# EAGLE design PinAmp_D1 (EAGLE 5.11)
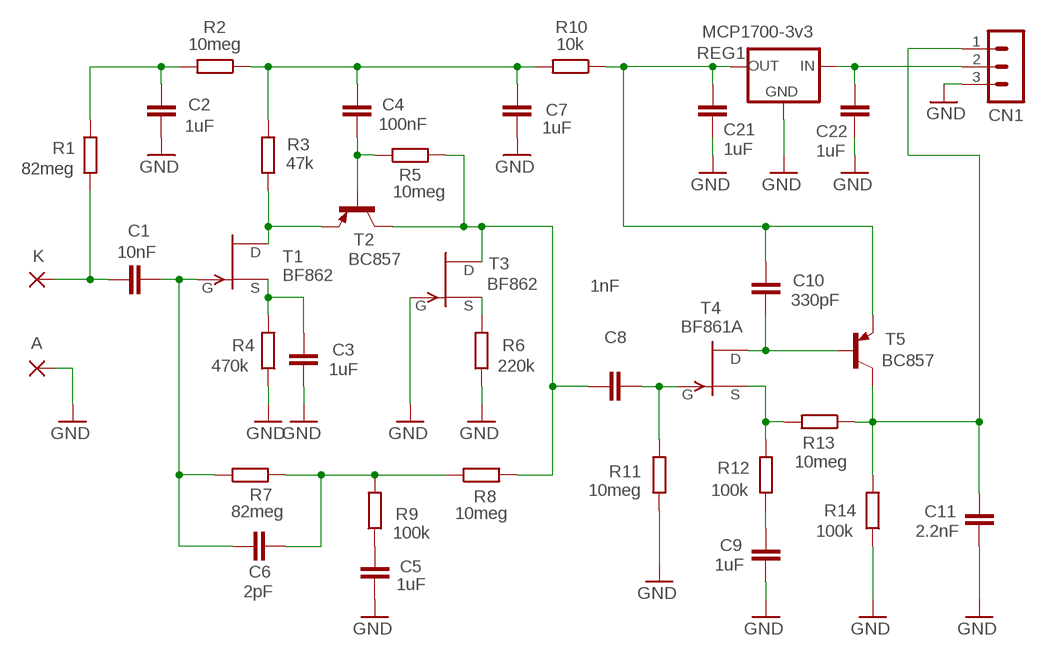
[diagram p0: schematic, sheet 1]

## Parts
A  A  WIREPAD1,6/0,8  [1,6/0,8]
C1  10nF  C-EUC0805  [C0805]
C2  1uF  C-EUC0603  [C0603]
C3  1uF  C-EUC0603  [C0603]
C4  100nF  C-EUC0603  [C0603]
C5  1uF  C-EUC0603  [C0603]
C6  2pF  C-EUC0603  [C0603]
C7  1uF  C-EUC0603  [C0603]
C8  1nF  C-EUC0603  [C0603]
C9  1uF  C-EUC0603  [C0603]
C10  330pF  C-EUC0603  [C0603]
C11  2.2nF  C-EUC0603  [C0603]
C21  1uF  C-EUC0603  [C0603]
C22  1uF  C-EUC0603  [C0603]
CN1  CN1  MA03-1W  [MA03-1W]
K  K  WIREPAD1,6/0,8  [1,6/0,8]
R1  82meg  R-EU_R0805  [R0805]
R2  10meg  R-EU_R0603  [R0603]
R3  47k  R-EU_R0603  [R0603]
R4  470k  R-EU_R0603  [R0603]
R5  10meg  R-EU_R0603  [R0603]
R6  220k  R-EU_R0603  [R0603]
R7  82meg  R-EU_R0805  [R0805]
R8  10meg  R-EU_R0805_L  [R0805_L]
R9  100k  R-EU_R0603  [R0603]
R10  10k  R-EU_R0603  [R0603]
R11  10meg  R-EU_R0603  [R0603]
R12  100k  R-EU_R0603  [R0603]
R13  10meg  R-EU_R0603  [R0603]
R14  100k  R-EU_R0603  [R0603]
REG1  MCP1700-3v3  MCP1700SOT23  [SOT23]
T1  BF862  BF861LR  [SOT23_L]
T2  BC857  -PNP-BC857  [SOT23_L]
T3  BF862  BF861LR  [SOT23_L]
T4  BF861A  BF861LR  [SOT23_L]
T5  BC857  -PNP-BC857  [SOT23_L]

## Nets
GND: A.1(P) C2.2 C3.1 C5.1 C7.2 C9.2 C11.2 C21.2 C22.2 CN1.3 R4.1 R6.1 R11.1 R14.1 REG1.1(GND) T3.3(G)
N$2: C2.1 R1.2 R2.2
N$3: C4.1 C7.1 R2.1 R3.2 R10.2
N$4: R3.1 T1.2(D) T2.2(E)
N$5: R6.2 T3.1(S)
N$6: C3.2 R4.2 T1.1(S)
N$7: C11.1 CN1.1 R13.1 R14.2 T5.3(C)
N$8: C6.2 R7.2 R8.1 R9.2
N$9: C4.2 R5.1 T2.1(B)
N$10: C5.2 R9.1
N$11: C1.2 C6.1 R7.1 T1.3(G)
N$12: C8.2 R11.2 T4.3(G)
N$13: C1.1 K.1(P) R1.1
N$15: C22.1 CN1.2 REG1.3(IN)
N$16: C8.1 R5.2 R8.2 T2.3(C) T3.2(D)
N$17: R12.2 R13.2 T4.1(S)
N$18: C9.1 R12.1
N$24: C10.1 T4.2(D) T5.1(B)
N$25: C10.2 C21.1 R10.1 REG1.2(OUT) T5.2(E)

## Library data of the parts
A = wirepad:WIREPAD: Wire PAD connect wire on PCB
C1-C11 C21 C22 = 00-LIVIO:C-EU: CAPACITOR, European symbol
CN1 = 03-con-lstb-M:MA03-1W
K = 00-LIVIO:WIREPAD: Wire PAD connect wire on PCB
R1-R14 = 00-LIVIO:R-EU_: RESISTOR, European symbol
REG1 = 00-LIVIO:MCP1700: Linear regulator Quescient courrent 1.8uA Input 2.3v to 6v Output 1.2v 1.8v 2.5v 3.0v 3.3v 5.0v
T1 T3 T4 = 00-LIVIO:BF861
T2 T5 = 00-LIVIO:*-PNP-: PNP Transistror

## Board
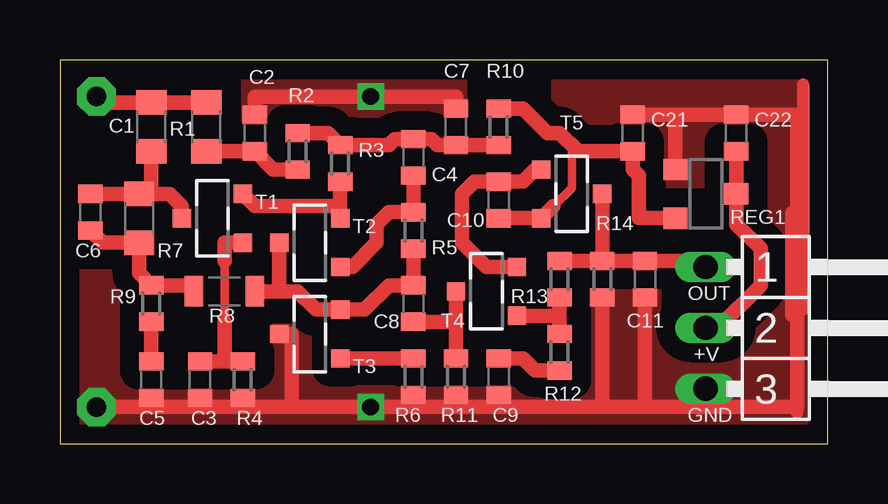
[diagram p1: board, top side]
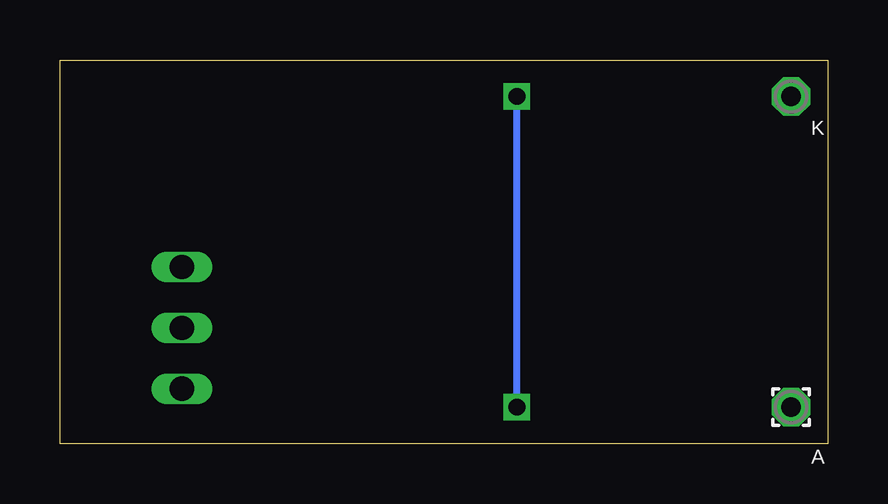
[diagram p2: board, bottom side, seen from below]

Size 32 x 16 mm. Coordinates in mm from the lower left corner, seen from the top.
Outline: 0,0 32,0 32,16 0,16 0,0
Copper layers (1*16): Top 0.035mm / dielectric 1.5mm / Bottom 0.035mm
Design rules "FastGcode-DesignRules": minimum track width 10mil, minimum drill 27mil, track to track 27mil, track to pad 27mil, pad to pad 27mil, via to via 27mil, smd to smd 27mil, copper to edge 27mil, drill to drill 8mil, minimum pad ring 5mil, minimum via ring 8mil, stop-mask expansion 4mil, vias tented up to drill 0mil, thermal gap 41mil

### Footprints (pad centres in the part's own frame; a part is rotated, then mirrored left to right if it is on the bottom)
1,6/0,8 = drill 0.813 pad 1.6 octagon: 1 0,0
C0805 = smd 1.016 x 1.27: 1 -1.016,0; 2 1.016,0
C0603 = smd 0.762 x 1.016: 1 -0.762,0; 2 0.762,0
MA03-1W = drill 1.016 long: 1 -2.54,0; 2 0,0; 3 2.54,0
R0805 = smd 1.016 x 1.27: 1 -1.016,0; 2 1.016,0
R0603 = smd 0.762 x 1.016: 1 -0.762,0; 2 0.762,0
R0805_L = smd 0.762 x 1.27: 1 -1.27,0; 2 1.27,0
SOT23 = smd 0.889 x 1.016: 1 -1.016,-1.27; 2 1.016,-1.27; 3 0,1.27
SOT23_L = smd 0.762 x 0.762: 1 -1.016,-1.27; 2 1.016,-1.27; 3 0,1.27

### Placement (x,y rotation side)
A  1.52,1.52 0 bottom
C1  3.81,13.21 270 top
C2  8.13,12.95 90 top
C3  5.84,2.67 90 top
C4  14.73,11.94 270 top
C5  3.81,2.67 90 top
C6  1.27,9.65 270 top
C7  16.51,13.21 90 top
C8  14.73,5.84 270 top
C9  18.29,2.79 270 top
C10  18.29,10.16 270 top
C11  24.38,6.86 270 top
C21  23.88,12.95 90 top
C22  28.19,12.95 90 top
CN1  26.92,4.83 270 top
K  1.52,14.48 0 bottom
R1  6.1,13.21 270 top
R2  9.91,12.19 270 top
R3  11.68,11.68 90 top
R4  7.62,2.67 90 top
R5  14.73,8.89 270 top
R6  14.73,2.79 90 top
R7  3.3,9.4 270 top
R8  6.86,6.35 0 top
R9  3.81,5.84 90 top
R10  18.29,13.21 270 top
R11  16.51,2.79 90 top
R12  20.83,3.81 90 top
R13  20.83,6.86 270 top
R14  22.61,6.86 90 top
REG1  26.92,10.41 270 top
T1  6.35,9.4 90 top
T2  10.41,8.38 90 top
T3  10.41,4.57 90 top
T4  17.78,6.35 90 top
T5  21.34,10.41 270 top

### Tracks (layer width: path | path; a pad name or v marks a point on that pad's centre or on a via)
GND  (via drill 0.7)
  Top 0.5: 30.99,5.59 30.99,14.99 30.99,9.65 30.48,9.65 30.48,5.33 30.73,5.33 30.73,1.52 | 30.73,1.52 30.73,1.27 30.73,1.52
  Top 0.6: A.1 3.81,1.52 | 3.81,1.52 5.84,1.52 | 5.84,1.52 7.62,1.52 | 7.62,1.52 9.65,1.52 | 9.65,1.52 v12.95,1.52 14.73,1.52 | 14.73,1.52 16.51,1.52 | 16.51,1.52 18.29,1.52 | 18.29,1.52 22.61,1.52 | 22.61,1.52 24.38,1.52 | 24.38,1.52 26.92,1.52 | 26.92,1.52 CN1.3 | 14.73,1.52 R6.1 | 7.62,1.52 R4.1 | 5.84,1.52 C3.1 | 9.65,1.52 9.65,4.57 T3.3 | 16.51,1.52 R11.1 | 18.29,1.52 C9.2 | 3.81,1.52 C5.1 | 24.38,1.52 C11.2 | 25.65,13.72 C22.2 30.73,13.72 30.73,9.4 30.73,5.33 30.73,1.52 26.92,1.52 | 25.65,13.72 REG1.1 | 22.61,1.52 R14.1 | C2.2 8.13,14.48 v12.95,14.48 16.51,14.48 C7.2 | 25.65,13.72 C21.2
  Bottom 0.3: v12.95,1.52 v12.95,14.48
  pour Top (isolate 0.8, rank 6, no thermals): -1,-1 33,-1 33,17 -1,17
N$2
  Top 0.6: R1.2 C2.1 8.89,11.43 R2.2
N$3
  Top 0.6: R2.1 11.18,12.95 R3.2 13.72,12.45 13.97,12.7 C4.1 15.49,12.7 15.75,12.45 C7.1 R10.2
N$4
  Top 0.6: 11.68,9.91 T2.2 | T1.2 8.13,9.91 11.68,9.91 | 11.68,9.91 11.68,10.16 R3.1
N$5
  Top 0.6: T3.1 R6.2
N$6
  Top 0.35: 6.86,5.08 6.86,7.62
  Top 0.6: R4.2 7.37,3.43 6.86,3.43 | 6.86,3.43 6.86,5.08 | 6.86,7.62 6.86,8.38 T1.1 | C3.2 6.86,3.43
N$7
  Top 0.6: R14.2 C11.1 25.91,7.62 26.16,7.37 CN1.1 | R13.1 R14.2 | R14.2 T5.3
N$8
  Top 0.6: R8.1 5.59,6.6 R9.2 3.3,7.11 R7.2 1.78,8.38 C6.2
N$9
  Top 0.6: T2.1 12.19,7.37 13.21,8.38 13.21,9.14 13.72,9.65 R5.1 C4.2
N$10
  Top 0.6: C5.2 R9.1
N$11
  Top 0.6: 3.81,10.41 R7.1 C6.1 | 3.81,10.41 4.57,10.41 5.08,9.91 T1.3 | 3.81,10.41 C1.2
N$12
  Top 0.6: C8.2 16.51,5.08 | 16.51,5.08 R11.2 | 16.51,5.08 T4.3
N$13
  Top 0.6: R1.1 C1.1 1.78,14.22 K.1
N$15
  Top 0.6: CN1.2 27.43,4.83 29.21,6.6 29.21,8.13 28.19,9.14 REG1.3 C22.1
N$16
  Top 0.6: R8.2 9.14,6.35 | 9.14,6.35 T2.3 | R5.2 C8.1 13.72,6.6 12.7,5.59 T3.2 10.67,5.59 9.91,6.35 9.14,6.35
N$17
  Top 0.6: T4.1 20.83,5.33 | 20.83,5.33 R13.2 | 20.83,5.33 20.83,4.83 R12.2
N$18
  Top 0.6: R12.1 19.81,3.05 19.3,3.56 C9.1
N$24
  Top 0.6: T4.2 17.78,7.37 16.76,8.38 16.76,10.41 17.27,10.92 C10.1 19.3,10.92 19.81,11.43 T5.1
N$25
  Top 0.35: 20.57,9.91 21.34,10.67 21.34,12.19 21.59,12.19
  Top 0.4: 21.59,12.19 21.84,12.19
  Top 0.6: 20.57,9.91 T5.2 C10.2 | REG1.2 24.13,9.4 24.13,11.18 23.88,11.43 C21.1 21.84,12.19 21.59,12.19 20.83,12.95 20.32,12.95 19.3,13.97 R10.1

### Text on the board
tNames: OUT | +V | GND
